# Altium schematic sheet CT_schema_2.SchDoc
size 278 x 192 mm
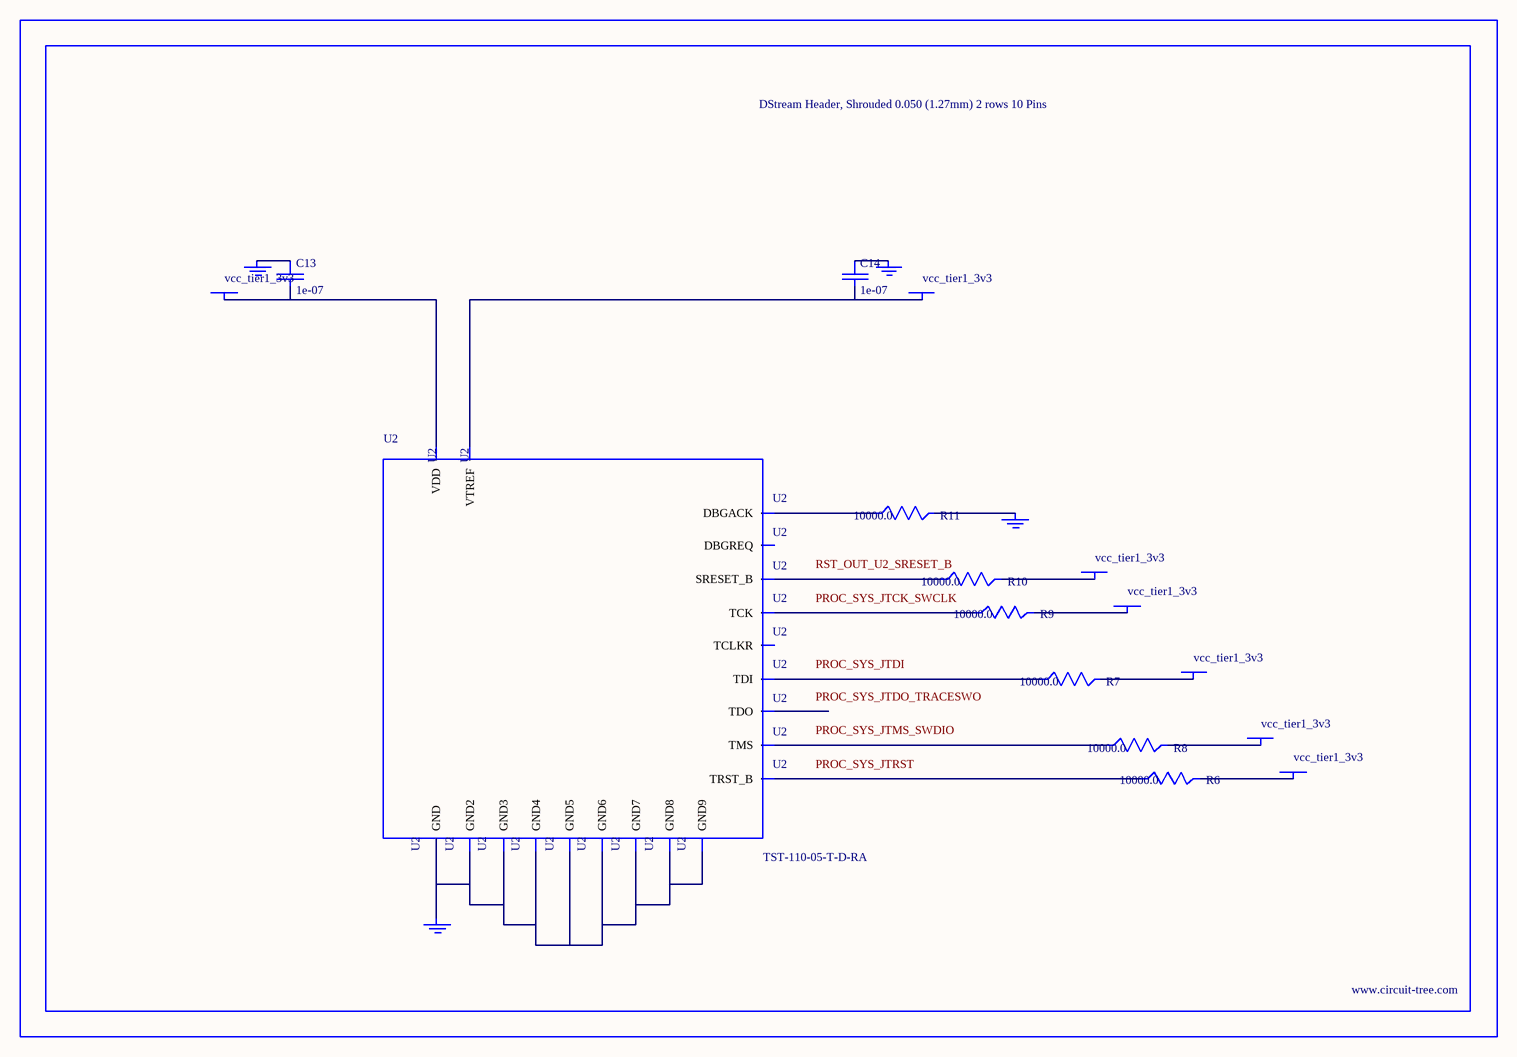
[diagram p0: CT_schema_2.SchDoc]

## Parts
BORDER1  (no value)
C13  1e-07  [C0402]
C14  1e-07  [C0402]
GND_INSTANCE_1_0  (no value)
GND_INSTANCE_1_1  (no value)
GND_INSTANCE_1_2  (no value)
GND_INSTANCE_1_3  (no value)
POWER_INSTANCE_1_0  vcc_tier1_3v3
POWER_INSTANCE_1_1  vcc_tier1_3v3
POWER_INSTANCE_1_2  vcc_tier1_3v3
POWER_INSTANCE_1_3  vcc_tier1_3v3
POWER_INSTANCE_1_4  vcc_tier1_3v3
POWER_INSTANCE_1_5  vcc_tier1_3v3
POWER_INSTANCE_1_6  vcc_tier1_3v3
R6  10000.0  [R0603]
R7  10000.0  [R0603]
R8  10000.0  [R0603]
R9  10000.0  [R0603]
R10  10000.0  [R0603]
R11  10000.0  [R0603]
U2  TST-110-05-T-D-RA  [TST-110-05-T-D-RA]

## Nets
NetC13_1: C13.1 GND_INSTANCE_1_1.0(GND)
NetC13_2: C13.2 POWER_INSTANCE_1_1.0(PWR) U2.2(VDD)
NetC14_1: C14.1 GND_INSTANCE_1_0.0(GND)
NetC14_2: C14.2 POWER_INSTANCE_1_0.0(PWR) U2.1(VTREF)
NetGND_INSTANCE_1_2_0: GND_INSTANCE_1_2.0(GND) R11.2
NetGND_INSTANCE_1_3_0: GND_INSTANCE_1_3.0(GND) U2.4(GND) U2.6(GND2) U2.8(GND3) U2.10(GND4) U2.12(GND5) U2.14(GND6) U2.16(GND7) U2.18(GND8) U2.20(GND9)
NetPOWER_INSTANCE_1_2_0: POWER_INSTANCE_1_2.0(PWR) R6.2
NetPOWER_INSTANCE_1_3_0: POWER_INSTANCE_1_3.0(PWR) R7.2
NetPOWER_INSTANCE_1_4_0: POWER_INSTANCE_1_4.0(PWR) R8.2
NetPOWER_INSTANCE_1_5_0: POWER_INSTANCE_1_5.0(PWR) R9.2
NetPOWER_INSTANCE_1_6_0: POWER_INSTANCE_1_6.0(PWR) R10.2
NetR6_1: R6.1 U2.3(TRST_B)
NetR7_1: R7.1 U2.5(TDI)
NetR8_1: R8.1 U2.7(TMS)
NetR9_1: R9.1 U2.9(TCK)
NetR10_1: R10.1 U2.15(SRESET_B)
NetR11_1: R11.1 U2.19(DBGACK)

Not connected (* = marked no-connect by the designer): U2 11(TCLKR) 13(TDO) 17(DBGREQ)

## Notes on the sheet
- Labels drawn without touching a wire or pin: PROC_SYS_JTCK_SWCLK, PROC_SYS_JTDI, PROC_SYS_JTDO_TRACESWO, PROC_SYS_JTMS_SWDIO, PROC_SYS_JTRST, RST_OUT_U2_SRESET_B

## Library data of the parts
BORDER1 = BORDER_PAGE1
C13 C14 = C0402C104K3RACTU
GND_INSTANCE_1_0-GND_INSTANCE_1_3 = GND
POWER_INSTANCE_1_0-POWER_INSTANCE_1_6 = PWR
R6-R11 = RC0603JR-0710KL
